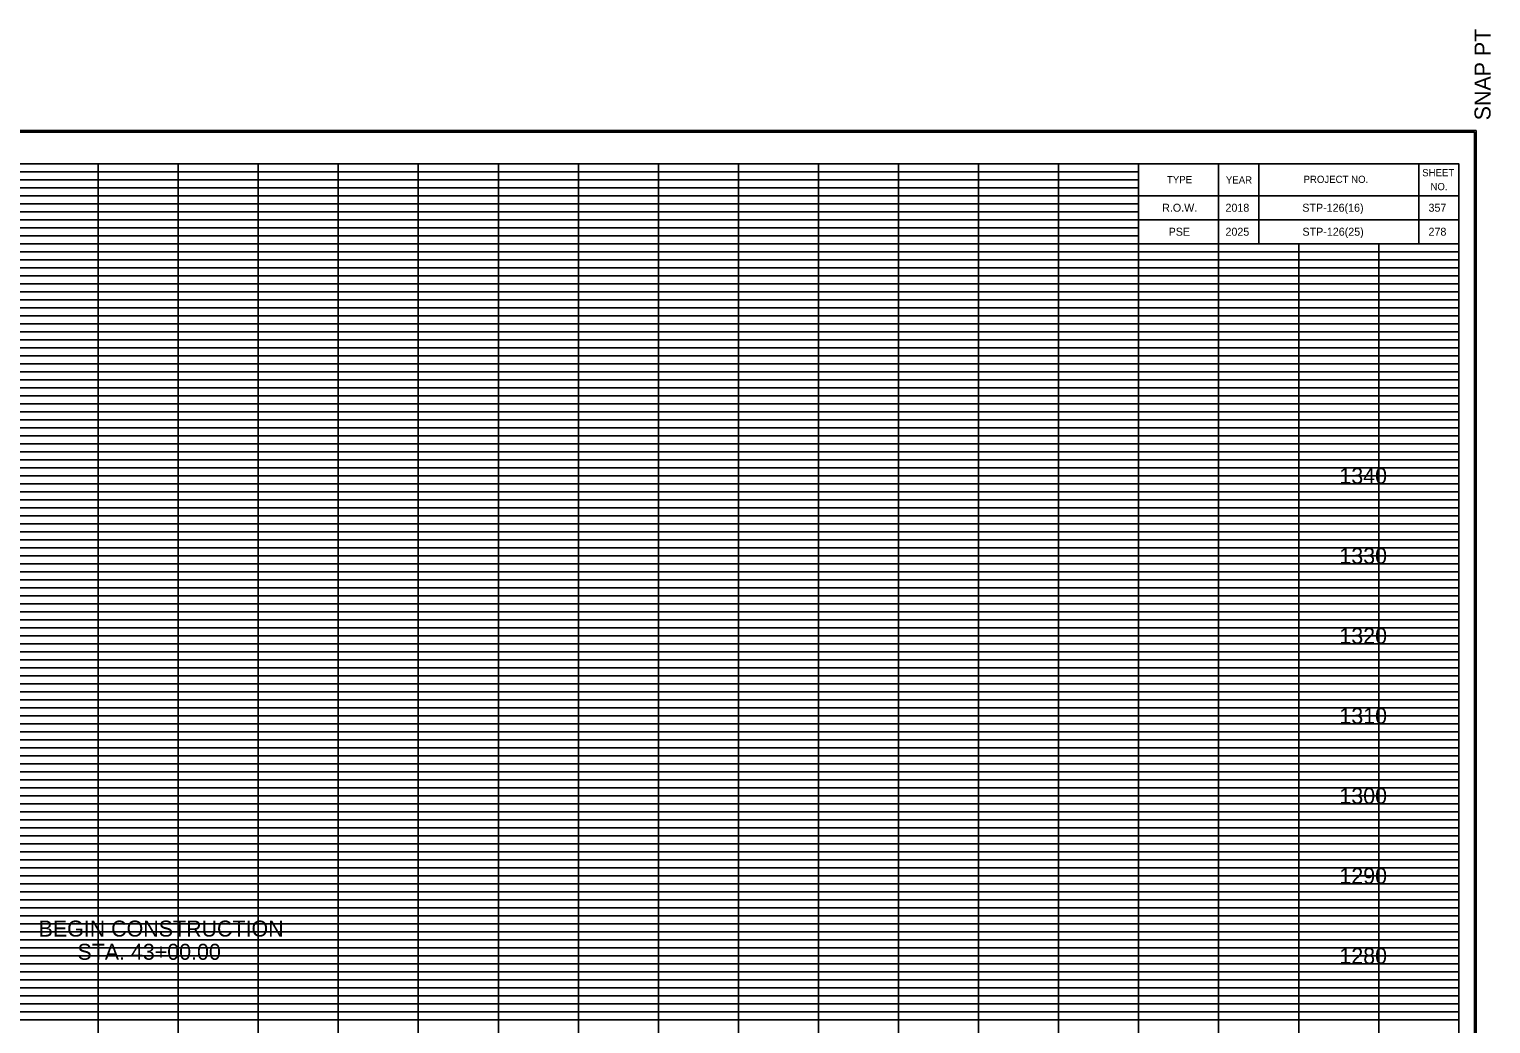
# Model space of a CAD drawing. Extents: x 980 to 1324, y 978 to 2847.
# Drawn here: x 1141.4 to 1324, y 1102.5 to 1226.8 of the extents above; entities that cross this region are included whole.
import ezdxf

# ---------------------------------------------------------------- set-up
doc = ezdxf.new("R2010")
doc.units = 0
for name, color, linetype in [('DESIGN - SCRATCH - User 1', 7, 'Continuous'), ('DESIGN - SHEET - Corner Text', 7, 'Continuous'), ('DESIGN - SHEET - Light Grid', 7, 'Continuous'), ('DESIGN - SHEET - Linework', 7, 'Continuous'), ('DESIGN - SHEET - Plot Shape', 7, 'Continuous'), ('DESIGN - TYPICAL - Text', 7, 'Continuous')]:
    doc.layers.add(name, color=color, linetype=linetype)

# ---------------------------------------------------------------- blocks, each defined once
blk = doc.blocks.new('XSTSHT')
at = {"layer": 'DESIGN - SCRATCH - User 1'}
for p, q in [((28.5, 20.45), (28.5, 20.45)), ((29.24, 20.45), (29.24, 20.45)), ((30.49, 20.45), (30.49, 20.45)), ((31.74, 20.45), (31.74, 20.45)), ((28.5, 20.15), (28.5, 20.15)), ((29.24, 20.15), (29.24, 20.15)), ((30.49, 20.15), (30.49, 20.15)), ((31.74, 20.15), (31.74, 20.15))]:
    blk.add_line(p, q, dxfattribs=at)
at = {"layer": 'DESIGN - SHEET - Light Grid'}
for p, q in [((8, 20.9), (16, 20.9)), ((16, 20.9), (24, 20.9)), ((24, 20.9), (28, 20.9)), ((8, 20.8), (16, 20.8)), ((8, 20.7), (16, 20.7)), ((16, 20.8), (24, 20.8)), ((16, 20.7), (24, 20.7)), ((24, 20.8), (28, 20.8)), ((24, 20.7), (28, 20.7)), ((8, 20.6), (16, 20.6)), ((8, 20.5), (16, 20.5)), ((16, 20.6), (24, 20.6)), ((16, 20.5), (24, 20.5)), ((24, 20.6), (28, 20.6)), ((24, 20.5), (28, 20.5)), ((8, 20.4), (16, 20.4)), ((8, 20.3), (16, 20.3)), ((16, 20.4), (24, 20.4)), ((16, 20.3), (24, 20.3)), ((24, 20.4), (28, 20.4)), ((24, 20.3), (28, 20.3)), ((8, 20.2), (16, 20.2)), ((8, 20.1), (16, 20.1)), ((16, 20.2), (24, 20.2)), ((16, 20.1), (24, 20.1)), ((24, 20.2), (28, 20.2)), ((24, 20.1), (28, 20.1)), ((8, 19.9), (16, 19.9)), ((8, 19.8), (16, 19.8)), ((16, 19.9), (24, 19.9)), ((16, 19.8), (24, 19.8)), ((24, 19.9), (32, 19.9)), ((24, 19.8), (32, 19.8)), ((8, 19.7), (16, 19.7)), ((8, 19.6), (16, 19.6)), ((16, 19.7), (24, 19.7)), ((16, 19.6), (24, 19.6)), ((24, 19.7), (32, 19.7)), ((24, 19.6), (32, 19.6)), ((8, 19.5), (16, 19.5)), ((8, 19.4), (16, 19.4)), ((16, 19.5), (24, 19.5)), ((16, 19.4), (24, 19.4)), ((24, 19.5), (32, 19.5)), ((24, 19.4), (32, 19.4)), ((8, 19.3), (16, 19.3)), ((8, 19.2), (16, 19.2)), ((16, 19.3), (24, 19.3)), ((16, 19.2), (24, 19.2)), ((24, 19.3), (32, 19.3)), ((24, 19.2), (32, 19.2)), ((8, 19.1), (16, 19.1)), ((16, 19.1), (24, 19.1)), ((24, 19.1), (32, 19.1)), ((8, 18.9), (16, 18.9)), ((16, 18.9), (24, 18.9)), ((24, 18.9), (32, 18.9)), ((8, 18.8), (16, 18.8)), ((8, 18.7), (16, 18.7)), ((16, 18.8), (24, 18.8)), ((16, 18.7), (24, 18.7)), ((24, 18.8), (32, 18.8)), ((24, 18.7), (32, 18.7)), ((8, 18.6), (16, 18.6)), ((8, 18.5), (16, 18.5)), ((16, 18.6), (24, 18.6)), ((16, 18.5), (24, 18.5)), ((24, 18.6), (32, 18.6)), ((24, 18.5), (32, 18.5)), ((8, 18.4), (16, 18.4)), ((8, 18.3), (16, 18.3)), ((16, 18.4), (24, 18.4)), ((16, 18.3), (24, 18.3)), ((24, 18.4), (32, 18.4)), ((24, 18.3), (32, 18.3)), ((8, 18.2), (16, 18.2)), ((8, 18.1), (16, 18.1)), ((16, 18.2), (24, 18.2)), ((16, 18.1), (24, 18.1)), ((24, 18.2), (32, 18.2)), ((24, 18.1), (32, 18.1)), ((8, 17.9), (16, 17.9)), ((16, 17.9), (24, 17.9)), ((24, 17.9), (32, 17.9)), ((8, 17.8), (16, 17.8)), ((16, 17.8), (24, 17.8)), ((24, 17.8), (32, 17.8)), ((8, 17.7), (16, 17.7)), ((8, 17.6), (16, 17.6)), ((16, 17.7), (24, 17.7)), ((16, 17.6), (24, 17.6)), ((24, 17.7), (32, 17.7)), ((24, 17.6), (32, 17.6)), ((8, 17.5), (16, 17.5)), ((8, 17.4), (16, 17.4)), ((16, 17.5), (24, 17.5)), ((16, 17.4), (24, 17.4)), ((24, 17.5), (32, 17.5)), ((24, 17.4), (32, 17.4)), ((8, 17.3), (16, 17.3)), ((8, 17.2), (16, 17.2)), ((16, 17.3), (24, 17.3)), ((16, 17.2), (24, 17.2)), ((24, 17.3), (32, 17.3)), ((24, 17.2), (32, 17.2)), ((8, 17.1), (16, 17.1)), ((16, 17.1), (24, 17.1)), ((24, 17.1), (32, 17.1)), ((8, 16.9), (16, 16.9)), ((16, 16.9), (24, 16.9)), ((24, 16.9), (32, 16.9)), ((8, 16.8), (16, 16.8)), ((8, 16.7), (16, 16.7)), ((16, 16.8), (24, 16.8)), ((16, 16.7), (24, 16.7)), ((24, 16.8), (32, 16.8)), ((24, 16.7), (32, 16.7)), ((8, 16.6), (16, 16.6)), ((8, 16.5), (16, 16.5)), ((16, 16.6), (24, 16.6)), ((16, 16.5), (24, 16.5)), ((24, 16.6), (32, 16.6)), ((24, 16.5), (32, 16.5)), ((8, 16.4), (16, 16.4)), ((8, 16.3), (16, 16.3)), ((16, 16.4), (24, 16.4)), ((16, 16.3), (24, 16.3)), ((24, 16.4), (32, 16.4)), ((24, 16.3), (32, 16.3)), ((8, 16.2), (16, 16.2)), ((8, 16.1), (16, 16.1)), ((16, 16.2), (24, 16.2)), ((16, 16.1), (24, 16.1)), ((24, 16.2), (32, 16.2)), ((24, 16.1), (32, 16.1)), ((8, 15.9), (16, 15.9)), ((16, 15.9), (24, 15.9)), ((24, 15.9), (32, 15.9)), ((8, 15.8), (16, 15.8)), ((16, 15.8), (24, 15.8)), ((24, 15.8), (32, 15.8)), ((8, 15.7), (16, 15.7)), ((8, 15.6), (16, 15.6)), ((16, 15.7), (24, 15.7)), ((16, 15.6), (24, 15.6)), ((24, 15.7), (32, 15.7)), ((24, 15.6), (32, 15.6)), ((8, 15.5), (16, 15.5)), ((8, 15.4), (16, 15.4)), ((16, 15.5), (24, 15.5)), ((16, 15.4), (24, 15.4)), ((24, 15.5), (32, 15.5)), ((24, 15.4), (32, 15.4)), ((8, 15.3), (16, 15.3)), ((8, 15.2), (16, 15.2)), ((16, 15.3), (24, 15.3)), ((16, 15.2), (24, 15.2)), ((24, 15.3), (32, 15.3)), ((24, 15.2), (32, 15.2)), ((8, 15.1), (16, 15.1)), ((16, 15.1), (24, 15.1)), ((24, 15.1), (32, 15.1)), ((8, 14.9), (16, 14.9)), ((8, 14.8), (16, 14.8)), ((16, 14.9), (24, 14.9)), ((16, 14.8), (24, 14.8)), ((24, 14.9), (32, 14.9)), ((24, 14.8), (32, 14.8)), ((8, 14.7), (16, 14.7)), ((16, 14.7), (24, 14.7)), ((24, 14.7), (32, 14.7)), ((8, 14.6), (16, 14.6)), ((8, 14.5), (16, 14.5)), ((16, 14.6), (24, 14.6)), ((16, 14.5), (24, 14.5)), ((24, 14.6), (32, 14.6)), ((24, 14.5), (32, 14.5)), ((8, 14.4), (16, 14.4)), ((8, 14.3), (16, 14.3)), ((16, 14.4), (24, 14.4)), ((16, 14.3), (24, 14.3)), ((24, 14.4), (32, 14.4)), ((24, 14.3), (32, 14.3)), ((8, 14.2), (16, 14.2)), ((8, 14.1), (16, 14.1)), ((16, 14.2), (24, 14.2)), ((16, 14.1), (24, 14.1)), ((24, 14.2), (32, 14.2)), ((24, 14.1), (32, 14.1)), ((8, 13.9), (16, 13.9)), ((16, 13.9), (24, 13.9)), ((24, 13.9), (32, 13.9)), ((8, 13.8), (16, 13.8)), ((8, 13.7), (16, 13.7)), ((16, 13.8), (24, 13.8)), ((16, 13.7), (24, 13.7)), ((24, 13.8), (32, 13.8)), ((24, 13.7), (32, 13.7)), ((8, 13.6), (16, 13.6)), ((16, 13.6), (24, 13.6)), ((24, 13.6), (32, 13.6)), ((8, 13.5), (16, 13.5)), ((8, 13.4), (16, 13.4)), ((16, 13.5), (24, 13.5)), ((16, 13.4), (24, 13.4)), ((24, 13.5), (32, 13.5)), ((24, 13.4), (32, 13.4)), ((8, 13.3), (16, 13.3)), ((8, 13.2), (16, 13.2)), ((16, 13.3), (24, 13.3)), ((16, 13.2), (24, 13.2)), ((24, 13.3), (32, 13.3)), ((24, 13.2), (32, 13.2)), ((8, 13.1), (16, 13.1)), ((16, 13.1), (24, 13.1)), ((24, 13.1), (32, 13.1)), ((8, 12.9), (16, 12.9)), ((8, 12.8), (16, 12.8)), ((16, 12.9), (24, 12.9)), ((16, 12.8), (24, 12.8)), ((24, 12.9), (32, 12.9)), ((24, 12.8), (32, 12.8)), ((8, 12.7), (16, 12.7)), ((16, 12.7), (24, 12.7)), ((24, 12.7), (32, 12.7)), ((8, 12.6), (16, 12.6)), ((8, 12.5), (16, 12.5)), ((16, 12.6), (24, 12.6)), ((16, 12.5), (24, 12.5)), ((24, 12.6), (32, 12.6)), ((24, 12.5), (32, 12.5)), ((8, 12.4), (16, 12.4)), ((8, 12.3), (16, 12.3)), ((16, 12.4), (24, 12.4)), ((16, 12.3), (24, 12.3)), ((24, 12.4), (32, 12.4)), ((24, 12.3), (32, 12.3)), ((8, 12.2), (16, 12.2)), ((8, 12.1), (16, 12.1)), ((16, 12.2), (24, 12.2)), ((16, 12.1), (24, 12.1)), ((24, 12.2), (32, 12.2)), ((24, 12.1), (32, 12.1)), ((8, 11.9), (16, 11.9)), ((16, 11.9), (24, 11.9)), ((24, 11.9), (32, 11.9)), ((8, 11.8), (16, 11.8)), ((8, 11.7), (16, 11.7)), ((16, 11.8), (24, 11.8)), ((16, 11.7), (24, 11.7)), ((24, 11.8), (32, 11.8)), ((24, 11.7), (32, 11.7)), ((8, 11.6), (16, 11.6)), ((16, 11.6), (24, 11.6)), ((24, 11.6), (32, 11.6)), ((8, 11.5), (16, 11.5)), ((8, 11.4), (16, 11.4)), ((16, 11.5), (24, 11.5)), ((16, 11.4), (24, 11.4)), ((24, 11.5), (32, 11.5)), ((24, 11.4), (32, 11.4)), ((8, 11.3), (16, 11.3)), ((8, 11.2), (16, 11.2)), ((16, 11.3), (24, 11.3)), ((16, 11.2), (24, 11.2)), ((24, 11.3), (32, 11.3)), ((24, 11.2), (32, 11.2)), ((8, 11.1), (16, 11.1)), ((16, 11.1), (24, 11.1)), ((24, 11.1), (32, 11.1)), ((8, 10.9), (16, 10.9)), ((8, 10.8), (16, 10.8)), ((16, 10.9), (24, 10.9)), ((16, 10.8), (24, 10.8)), ((24, 10.9), (32, 10.9)), ((24, 10.8), (32, 10.8)), ((8, 10.7), (16, 10.7)), ((8, 10.6), (16, 10.6)), ((16, 10.7), (24, 10.7)), ((16, 10.6), (24, 10.6)), ((24, 10.7), (32, 10.7)), ((24, 10.6), (32, 10.6)), ((8, 10.5), (16, 10.5)), ((16, 10.5), (24, 10.5)), ((24, 10.5), (32, 10.5)), ((8, 10.4), (16, 10.4)), ((8, 10.3), (16, 10.3)), ((16, 10.4), (24, 10.4)), ((16, 10.3), (24, 10.3)), ((24, 10.4), (32, 10.4)), ((24, 10.3), (32, 10.3))]:
    blk.add_line(p, q, dxfattribs=at)
at = {"layer": 'DESIGN - SHEET - Linework'}
for p, q in [((-1.823, 21.414), (32.217, 21.414)), ((32.217, 21.414), (32.217, -0.414)), ((15, 0), (15, 21)), ((16, 0), (16, 21)), ((17, 0), (17, 21)), ((18, 0), (18, 21)), ((19, 0), (19, 21)), ((20, 0), (20, 21)), ((21, 0), (21, 21)), ((22, 0), (22, 21)), ((23, 0), (23, 21)), ((24, 0), (24, 21)), ((25, 0), (25, 21)), ((26, 0), (26, 21)), ((27, 0), (27, 21)), ((0, 20), (28, 20)), ((28, 0), (28, 20)), ((29, 0), (29, 20)), ((30, 0), (30, 20)), ((31, 0), (31, 20)), ((0, 19), (32, 19)), ((0, 18), (32, 18)), ((0, 17), (32, 17)), ((0, 16), (32, 16)), ((0, 15), (32, 15)), ((0, 14), (32, 14)), ((0, 13), (32, 13)), ((0, 12), (32, 12)), ((0, 11), (32, 11))]:
    blk.add_line(p, q, dxfattribs=at)
for points in [[(0, 21), (0, 0), (32, 0), (32, 21), (0, 21)], [(28, 21), (28, 20), (32, 20), (32, 21), (31.5, 21), (31.5, 20), (29.5, 20), (29.5, 21), (29, 21), (29, 20), (32, 20), (28, 20), (28, 20.3), (32, 20.3), (32, 20.6), (28, 20.6)]]:
    blk.add_lwpolyline(points, dxfattribs=at)
at = {"layer": 'DESIGN - SHEET - Plot Shape'}
for points in [[(-1.803, 21.394), (32.197, 21.394), (32.197, -0.394), (-1.803, -0.394)], [(-0.85, 21), (32, 21), (32, -0.25), (-0.85, -0.25)]]:
    blk.add_lwpolyline(points, close=True, dxfattribs=at)
at = {"layer": 'DESIGN - SHEET - Corner Text'}
blk.add_text('  SNAP PT', height=0.2, rotation=90, dxfattribs=at).set_placement((32.397, 21.394))
for s, p in [('TYPE', (28.354, 20.756)), ('YEAR', (29.09, 20.752)), ('PROJECT NO.', (30.06, 20.76)), ('SHEET', (31.543, 20.843)), ('NO.', (31.646, 20.669))]:
    blk.add_text(s, height=0.09, dxfattribs=at).set_placement(p)

msp = doc.modelspace()

# ---------------------------------------------------------------- linework, layer by layer
at = {"layer": 'DESIGN - SHEET - Plot Shape'}
msp.add_lwpolyline([(991.5, 997.5), (1320, 997.5), (1320, 1210), (991.5, 1210)], close=True, dxfattribs=at)

# ---------------------------------------------------------------- block references
at = {"layer": 'DESIGN - SHEET - Plot Shape', "xscale": 10, "yscale": 10}
msp.add_blockref('XSTSHT', (1000, 1000), dxfattribs=at)

# ---------------------------------------------------------------- texts
at = {"layer": 'DESIGN - SHEET - Corner Text'}
for s, p in [('R.O.W.', (1282.94, 1204)), ('2018', (1290.85, 1204)), ('STP-126(16)', (1300.45, 1204)), ('357', (1316.22, 1204)), ('PSE', (1283.75, 1201)), ('2025', (1290.85, 1201)), ('STP-126(25)', (1300.47, 1201)), ('278', (1316.22, 1201))]:
    msp.add_text(s, height=1, dxfattribs=at).set_placement(p)
at = {"layer": 'DESIGN - TYPICAL - Text'}
for s, p in [('     1340     ', (1301.37, 1170)), ('     1330     ', (1301.37, 1160)), ('     1320     ', (1301.37, 1150)), ('     1310     ', (1301.37, 1140)), ('     1300     ', (1301.37, 1130)), ('     1290     ', (1301.37, 1120)), ('BEGIN CONSTRUCTION', (1142.56, 1113.41)), ('STA. 43+00.00', (1147.41, 1110.51)), ('     1280     ', (1301.37, 1110))]:
    msp.add_text(s, height=2, dxfattribs=at).set_placement(p)

doc.saveas('drawing.dxf')
